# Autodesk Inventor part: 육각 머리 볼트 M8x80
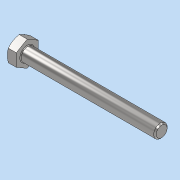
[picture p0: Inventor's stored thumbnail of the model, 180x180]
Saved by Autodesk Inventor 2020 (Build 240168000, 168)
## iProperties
Created: 2025-01
Part Number: 육각 머리 볼트 M8x80
Material: 강철, 연강
Description: 6각 머리 볼트 및 6각 머리 나사
Document SubType Name: Modeling
Designer: 1강의실14
Density: 7.85 g/cm^3
Appearance: 기본값
Author: jhkim
Sending System: Autodesk Inventor 2025
Preprocessor: ST-DEVELOPER v20
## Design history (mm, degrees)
feature "Solid1"
node "솔리드1"
